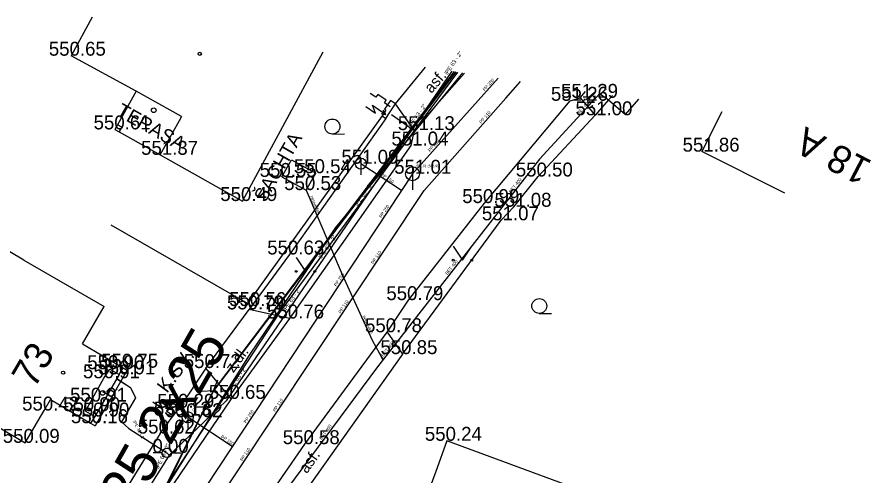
# Model space of a CAD drawing. Extents: x -669995 to -669686, y -1125551 to -1125263.
# Drawn here: x -669817.31 to -669771.34, y -1125299.08 to -1125274.36 of the extents above; entities that cross this region are included whole.
import ezdxf

# ---------------------------------------------------------------- set-up
doc = ezdxf.new("R2010")
doc.units = 0
for name, color, linetype in [('G_Bod_tecka', 7, 'Continuous'), ('G_Bod_vyska', 7, 'Continuous'), ('G_Budovy-znacky', 7, 'Continuous'), ('G_Budovy_Objekty', 7, 'Continuous'), ('G_Budovy_vstupy', 7, 'Continuous'), ('G_Cesty_Schody', 7, 'Continuous'), ('G_Cisla_popisna', 7, 'Continuous'), ('G_Plochy_zpevnene', 7, 'Continuous'), ('G_Ploty', 7, 'Continuous'), ('G_Ploty_vstupy', 7, 'Continuous'), ('G_Popisy_objektu', 7, 'Continuous'), ('G_Popisy_povrchu', 7, 'Continuous'), ('G_Poznamky_odkaz', 7, 'Continuous'), ('G_Site-kanalizace', 7, 'Continuous'), ('G_Site-Rozvadece', 7, 'Continuous'), ('G_Site-vodovod', 7, 'Continuous'), ('G_Z_ELsilove_nadz_kotovane', 7, 'Continuous'), ('G_Z_ELsilove_podz_kotovane', 7, 'Continuous'), ('G_Z_KANAL_podz_kotovane', 7, 'Continuous'), ('G_Z_KANAL_podz_priblizne', 7, 'Continuous'), ('G_Z_PLYNY_podz_geodeticky', 7, 'Continuous'), ('G_Z_SPOJE_podz_geodeticky', 7, 'Continuous'), ('G_Z_SPOJE_podz_kotovane', 7, 'Continuous'), ('G_Z_SPOJE_podz_priblizne', 7, 'Continuous'), ('G_Z_VODA_podz_kotovane', 7, 'Continuous'), ('G_Zelen-okraj', 7, 'Continuous'), ('G_Zelen-Znacky', 7, 'Continuous'), ('Vrstva 11', 7, 'Continuous'), ('Vrstva 13', 7, 'Continuous'), ('Vrstva 17', 7, 'Continuous'), ('Vrstva 2', 7, 'Continuous'), ('Vrstva 21', 7, 'Continuous'), ('Vrstva 26', 7, 'Continuous'), ('Vrstva 3', 7, 'Continuous'), ('Vrstva 4', 7, 'Continuous'), ('Vrstva 5', 7, 'Continuous'), ('Vrstva 6', 7, 'Continuous'), ('Vrstva 8', 7, 'Continuous')]:
    doc.layers.add(name, color=color, linetype=linetype)

msp = doc.modelspace()

# ---------------------------------------------------------------- linework, layer by layer
at = {"layer": 'G_Bod_tecka'}
for p, q in [((-669814.4, -1125276.44), (-669814.4, -1125276.44)), ((-669787, -1125278.71), (-669787, -1125278.71)), ((-669787.53, -1125278.87), (-669787.53, -1125278.87)), ((-669786.18, -1125279.65), (-669786.18, -1125279.65)), ((-669812.05, -1125280.41), (-669812.05, -1125280.41)), ((-669795.93, -1125280.45), (-669795.93, -1125280.45)), ((-669796.11, -1125281.28), (-669796.11, -1125281.28)), ((-669809.61, -1125281.78), (-669809.61, -1125281.78)), ((-669780.44, -1125281.61), (-669780.44, -1125281.61)), ((-669798.8, -1125282.26), (-669798.8, -1125282.26)), ((-669803.06, -1125282.97), (-669803.06, -1125282.97)), ((-669801.22, -1125282.77), (-669801.22, -1125282.77)), ((-669796.02, -1125282.8), (-669796.02, -1125282.8)), ((-669789.25, -1125282.95), (-669789.25, -1125282.95)), ((-669801.74, -1125283.68), (-669801.74, -1125283.68)), ((-669805.18, -1125284.27), (-669805.18, -1125284.27)), ((-669792.15, -1125284.38), (-669792.15, -1125284.38)), ((-669790.56, -1125284.58), (-669790.56, -1125284.58)), ((-669791.24, -1125285.31), (-669791.24, -1125285.31)), ((-669802.64, -1125287.15), (-669802.64, -1125287.15)), ((-669796.24, -1125289.61), (-669796.24, -1125289.61)), ((-669804.82, -1125290.11), (-669804.82, -1125290.11)), ((-669804.69, -1125289.93), (-669804.69, -1125289.93)), ((-669802.65, -1125290.6), (-669802.65, -1125290.6)), ((-669797.39, -1125291.34), (-669797.39, -1125291.34)), ((-669796.56, -1125292.52), (-669796.56, -1125292.52)), ((-669812.32, -1125293.33), (-669812.32, -1125293.33)), ((-669811.6, -1125293.25), (-669811.6, -1125293.25)), ((-669807.15, -1125293.27), (-669807.15, -1125293.27)), ((-669812.63, -1125293.82), (-669812.63, -1125293.82)), ((-669811.81, -1125293.61), (-669811.81, -1125293.61)), ((-669813.33, -1125295.08), (-669813.33, -1125295.08)), ((-669805.79, -1125294.93), (-669805.79, -1125294.93)), ((-669815.85, -1125295.56), (-669815.85, -1125295.56)), ((-669813.62, -1125295.59), (-669813.62, -1125295.59)), ((-669808.9, -1125295.83), (-669808.9, -1125295.83)), ((-669808.57, -1125295.41), (-669808.57, -1125295.41)), ((-669813.35, -1125296.24), (-669813.35, -1125296.24)), ((-669813.12, -1125295.88), (-669813.12, -1125295.88)), ((-669808.12, -1125295.92), (-669808.12, -1125295.92)), ((-669809.61, -1125296.8), (-669809.61, -1125296.8)), ((-669794.17, -1125297.19), (-669794.17, -1125297.19)), ((-669816.87, -1125297.3), (-669816.87, -1125297.3)), ((-669801.82, -1125297.37), (-669801.82, -1125297.37)), ((-669809.24, -1125297.84), (-669809.24, -1125297.84))]:
    msp.add_line(p, q, dxfattribs=at)
at = {"layer": 'G_Budovy-znacky'}
for centre, radius in [((-669807.47, -1125276.34), 0.0875), ((-669809.951, -1125279.38), 0.125), ((-669814.831, -1125293.52), 0.0875), ((-669812.7, -1125294.61), 0.125)]:
    msp.add_circle(centre, radius, dxfattribs=at)
at = {"layer": 'G_Budovy_Objekty'}
for p, q in [((-669813.267, -1125274.359), (-669814.4, -1125276.44)), ((-669810.89, -1125278.35), (-669814.4, -1125276.44)), ((-669805.18, -1125284.27), (-669800.837, -1125276.231)), ((-669810.89, -1125278.35), (-669811.91, -1125280.17)), ((-669808.45, -1125279.72), (-669810.89, -1125278.35)), ((-669808.45, -1125279.72), (-669808.58, -1125279.95)), ((-669779.365, -1125279.465), (-669780.44, -1125281.61)), ((-669811.91, -1125280.17), (-669812.05, -1125280.41)), ((-669811.67, -1125280.3), (-669811.91, -1125280.17)), ((-669812.05, -1125280.41), (-669811.81, -1125280.55)), ((-669811.67, -1125280.3), (-669811.81, -1125280.55)), ((-669811.81, -1125280.55), (-669809.61, -1125281.78)), ((-669809.61, -1125281.78), (-669809.27, -1125281.17)), ((-669809.61, -1125281.78), (-669805.18, -1125284.27)), ((-669775.97, -1125283.85), (-669780.44, -1125281.61)), ((-669816.95, -1125287.46), (-669821.67, -1125284.62)), ((-669816.95, -1125287.46), (-669812.62, -1125289.95)), ((-669813.78, -1125291.97), (-669812.62, -1125289.95)), ((-669813.78, -1125291.97), (-669811.6, -1125293.25)), ((-669812.63, -1125293.82), (-669812.32, -1125293.33)), ((-669812.32, -1125293.33), (-669811.81, -1125293.61)), ((-669811.81, -1125293.61), (-669811.6, -1125293.25)), ((-669811.81, -1125293.61), (-669813.12, -1125295.88)), ((-669821.18, -1125294.77), (-669816.87, -1125297.3)), ((-669815.85, -1125295.56), (-669815.51, -1125294.97)), ((-669815.51, -1125294.97), (-669813.35, -1125296.24)), ((-669813.62, -1125295.59), (-669813.33, -1125295.08)), ((-669816.87, -1125297.3), (-669815.85, -1125295.56)), ((-669813.62, -1125295.59), (-669813.12, -1125295.88)), ((-669813.12, -1125295.88), (-669813.35, -1125296.24)), ((-669794.17, -1125297.19), (-669794.77, -1125298.84)), ((-669779.82, -1125302.48), (-669794.17, -1125297.19))]:
    msp.add_line(p, q, dxfattribs=at)
at = {"layer": 'G_Budovy_vstupy'}
for p, q in [((-669808.58, -1125279.95), (-669809.27, -1125281.17)), ((-669813.33, -1125295.08), (-669812.63, -1125293.82)), ((-669794.77, -1125298.84), (-669796.57, -1125303.72))]:
    msp.add_line(p, q, dxfattribs=at)
at = {"layer": 'G_Cesty_Schody'}
for p, q in [((-669803.06, -1125282.97), (-669802.54, -1125282.06)), ((-669802.54, -1125282.06), (-669801.22, -1125282.77)), ((-669803.06, -1125282.97), (-669801.74, -1125283.68)), ((-669801.74, -1125283.68), (-669801.22, -1125282.77))]:
    msp.add_line(p, q, dxfattribs=at)
for points in [[(-669793.221, -1125277.378), (-669795.93, -1125280.45)], [(-669802.65, -1125290.6), (-669805.79, -1125294.93)]]:
    msp.add_lwpolyline(points, dxfattribs=at)
at = {"layer": 'G_Plochy_zpevnene'}
for p, q in [((-669787, -1125278.71), (-669786.18, -1125279.65)), ((-669785.96, -1125278.472), (-669785.46, -1125278.82)), ((-669795.93, -1125280.45), (-669796.93, -1125279.04)), ((-669792.15, -1125284.38), (-669787.53, -1125278.87)), ((-669796.24, -1125289.61), (-669792.15, -1125284.38)), ((-669797.39, -1125291.34), (-669796.24, -1125289.61)), ((-669801.82, -1125297.37), (-669797.39, -1125291.34)), ((-669811.38, -1125293.38), (-669813.11, -1125296.38)), ((-669811.6, -1125293.25), (-669811.38, -1125293.38)), ((-669813.35, -1125296.24), (-669813.11, -1125296.38)), ((-669804.96, -1125301.91), (-669801.82, -1125297.37))]:
    msp.add_line(p, q, dxfattribs=at)
for points in [[(-669787, -1125278.71), (-669786.697, -1125278.361)], [(-669787.53, -1125278.87), (-669787, -1125278.71)], [(-669795.93, -1125280.45), (-669796.11, -1125281.28), (-669802.65, -1125290.6)], [(-669802.65, -1125290.6), (-669804.82, -1125290.11)], [(-669797.39, -1125291.34), (-669796.56, -1125292.52)], [(-669805.79, -1125294.93), (-669807.15, -1125293.27)], [(-669805.79, -1125294.93), (-669810.6, -1125302.02), (-669813.3, -1125306.54), (-669816.06, -1125312.52), (-669819.42, -1125319.54), (-669819.78, -1125320.24), (-669820.3, -1125320.5), (-669820.46, -1125320.59)]]:
    msp.add_lwpolyline(points, dxfattribs=at)
at = {"layer": 'G_Ploty'}
for p, q in [((-669785.46, -1125278.82), (-669785.251, -1125278.579)), ((-669797.66, -1125279.68), (-669804.91, -1125289.8)), ((-669789.25, -1125282.95), (-669786.18, -1125279.65)), ((-669804.91, -1125289.8), (-669812.24, -1125285.58)), ((-669804.69, -1125289.93), (-669804.91, -1125289.8)), ((-669804.69, -1125289.93), (-669804.82, -1125290.11))]:
    msp.add_line(p, q, dxfattribs=at)
for points in [[(-669797.45, -1125279.82), (-669802.64, -1125287.15), (-669804.69, -1125289.93)], [(-669790.56, -1125284.58), (-669789.25, -1125282.95)], [(-669796.56, -1125292.52), (-669791.24, -1125285.31)], [(-669807.15, -1125293.27), (-669808.57, -1125295.41)], [(-669809.61, -1125296.8), (-669814.94, -1125305.46)]]:
    msp.add_lwpolyline(points, dxfattribs=at)
at = {"layer": 'G_Ploty_vstupy'}
for p, q in [((-669796.93, -1125279.04), (-669795.318, -1125277.062)), ((-669785.46, -1125278.82), (-669786.18, -1125279.65)), ((-669790.56, -1125284.58), (-669791.24, -1125285.31))]:
    msp.add_line(p, q, dxfattribs=at)
for points in [[(-669807.15, -1125293.27), (-669804.82, -1125290.11)], [(-669796.56, -1125292.52), (-669802.85, -1125301.41)], [(-669809.61, -1125296.8), (-669808.9, -1125295.85)]]:
    msp.add_lwpolyline(points, dxfattribs=at)
at = {"layer": 'G_Site-kanalizace'}
for p, q in [((-669798.8, -1125281.96), (-669798.8, -1125282.86)), ((-669796.02, -1125282.425), (-669796.02, -1125283.675)), ((-669808.12, -1125295.62), (-669808.12, -1125296.52))]:
    msp.add_line(p, q, dxfattribs=at)
for centre, radius in [((-669798.8, -1125282.26), 0.3), ((-669796.02, -1125282.8), 0.375), ((-669808.12, -1125295.92), 0.3)]:
    msp.add_circle(centre, radius, dxfattribs=at)
at = {"layer": 'G_Site-Rozvadece'}
for p, q in [((-669798.526, -1125279.183), (-669798.005, -1125279.53)), ((-669798.005, -1125279.53), (-669798.178, -1125279.114)), ((-669798.178, -1125279.114), (-669797.45, -1125279.6)), ((-669797.715, -1125279.555), (-669797.45, -1125279.6)), ((-669797.45, -1125279.6), (-669797.593, -1125279.372)), ((-669810.001, -1125295.093), (-669809.484, -1125295.445)), ((-669809.484, -1125295.445), (-669809.653, -1125295.028)), ((-669809.653, -1125295.028), (-669808.93, -1125295.52)), ((-669808.93, -1125295.52), (-669809.07, -1125295.291)), ((-669809.194, -1125295.473), (-669808.93, -1125295.52))]:
    msp.add_line(p, q, dxfattribs=at)
msp.add_lwpolyline([(-669797.23, -1125279.19), (-669797.535, -1125278.985), (-669797.434, -1125278.833), (-669797.893, -1125278.526), (-669797.996, -1125278.678), (-669798.302, -1125278.475)], dxfattribs=at)
for points in [[(-669796.93, -1125279.04), (-669797.21, -1125278.85), (-669797.53, -1125279.33), (-669797.46, -1125279.38), (-669797.66, -1125279.68), (-669797.45, -1125279.82), (-669797.25, -1125279.52)], [(-669808.93, -1125295.14), (-669809.26, -1125295.58), (-669808.9, -1125295.85), (-669808.57, -1125295.41)]]:
    msp.add_lwpolyline(points, close=True, dxfattribs=at)
at = {"layer": 'G_Site-vodovod'}
for p, q in [((-669809.49, -1125297.84), (-669809.99, -1125297.84)), ((-669808.99, -1125297.84), (-669808.49, -1125297.84))]:
    msp.add_line(p, q, dxfattribs=at)
msp.add_circle((-669809.24, -1125297.84), 0.25, dxfattribs=at)
at = {"layer": 'G_Z_ELsilove_nadz_kotovane'}
for points in [[(-669822.83, -1125326.67), (-669806.73, -1125294.49), (-669793.764, -1125277.296)], [(-669806.73, -1125294.49), (-669806.505, -1125293.909)], [(-669806.73, -1125294.49), (-669807.359, -1125294.525)], [(-669806.73, -1125294.49), (-669806.213, -1125294.859)]]:
    msp.add_lwpolyline(points, dxfattribs=at)
at = {"layer": 'G_Z_ELsilove_podz_kotovane'}
msp.add_lwpolyline([(-669793.678, -1125277.309), (-669806.73, -1125294.49), (-669822.69, -1125326.67), (-669837.43, -1125364.93), (-669849.93, -1125407.07), (-669860.28, -1125448.68)], dxfattribs=at)
at = {"layer": 'G_Z_KANAL_podz_kotovane'}
for p, q in [((-669791.4, -1125277.652), (-669796.02, -1125282.8)), ((-669796.62, -1125283.7), (-669798.8, -1125282.26))]:
    msp.add_line(p, q, dxfattribs=at)
for points in [[(-669837.47, -1125406.42), (-669844.1, -1125405.26), (-669833.36, -1125371.21), (-669821.31, -1125332.23), (-669811.44, -1125307.86), (-669795.39, -1125283.71), (-669791, -1125278.72), (-669790.199, -1125277.833)], [(-669796.62, -1125283.7), (-669798.8, -1125282.26)], [(-669796.02, -1125282.8), (-669812.36, -1125307.58), (-669819.67, -1125324.06)], [(-669801.74, -1125283.68), (-669799.8, -1125288.23), (-669798.19, -1125291.77), (-669797.79, -1125292.49), (-669797.61, -1125292.82)], [(-669805.72, -1125297.5), (-669805.72, -1125297.5), (-669808.12, -1125295.92)]]:
    msp.add_lwpolyline(points, dxfattribs=at)
at = {"layer": 'G_Z_KANAL_podz_priblizne'}
msp.add_lwpolyline([(-669785.926, -1125278.477), (-669789.18, -1125282.01), (-669797.9, -1125293.2), (-669805.95, -1125304.06)], dxfattribs=at)
at = {"layer": 'G_Z_PLYNY_podz_geodeticky'}
for points in [[(-669837.38, -1125359.92), (-669836.39, -1125358.74), (-669831.49, -1125357.25), (-669831.11, -1125356.92), (-669827.75, -1125345.68), (-669825.44, -1125337.89), (-669825.15, -1125336.78), (-669824.89, -1125336.1), (-669824.26, -1125333.86), (-669824.2, -1125333.72), (-669824.11, -1125333.34), (-669824.01, -1125332.89), (-669822.73, -1125329.33), (-669822.53, -1125328.7), (-669820.54, -1125322.64), (-669816.69, -1125313.26), (-669812.22, -1125303.65), (-669812, -1125303.3), (-669811.72, -1125302.91), (-669809.57, -1125300.17), (-669804.79, -1125292.58), (-669800.14, -1125285.7), (-669795.88, -1125280.51), (-669793.302, -1125277.366)], [(-669797.15, -1125279.61), (-669795.88, -1125280.51)]]:
    msp.add_lwpolyline(points, dxfattribs=at)
at = {"layer": 'G_Z_SPOJE_podz_geodeticky'}
msp.add_lwpolyline([(-669821.65, -1125324.81), (-669819.63, -1125318.51), (-669812.69, -1125304.83), (-669803.17, -1125290.27), (-669793.576, -1125277.325)], dxfattribs=at)
at = {"layer": 'G_Z_SPOJE_podz_kotovane'}
msp.add_lwpolyline([(-669821.65, -1125324.81), (-669819.63, -1125318.51), (-669812.69, -1125304.83), (-669803.17, -1125290.27), (-669793.576, -1125277.325)], dxfattribs=at)
at = {"layer": 'G_Z_SPOJE_podz_priblizne'}
msp.add_lwpolyline([(-669821.65, -1125324.81), (-669819.63, -1125318.51), (-669812.69, -1125304.83), (-669803.17, -1125290.27), (-669793.576, -1125277.325)], dxfattribs=at)
at = {"layer": 'G_Z_VODA_podz_kotovane'}
for points in [[(-669793.904, -1125277.275), (-669806.05, -1125295.04), (-669809.12, -1125297.97), (-669810.25, -1125299.77), (-669811.13, -1125301.2), (-669814.74, -1125307.05), (-669820.1, -1125318), (-669821.98, -1125322.82), (-669822.36, -1125327.56), (-669822.7, -1125328.38), (-669827.24, -1125342.56), (-669833.54, -1125362.52), (-669834.09, -1125363.24)], [(-669811.94, -1125293.84), (-669811.2, -1125294.32), (-669810.93, -1125294.88), (-669811.69, -1125296.16), (-669811.3, -1125296.52), (-669809.24, -1125297.84), (-669809.12, -1125297.97)]]:
    msp.add_lwpolyline(points, dxfattribs=at)
at = {"layer": 'G_Zelen-okraj'}
for p, q in [((-669785.46, -1125278.82), (-669784.55, -1125279.61)), ((-669784.55, -1125279.61), (-669783.841, -1125278.791))]:
    msp.add_line(p, q, dxfattribs=at)
at = {"layer": 'G_Zelen-Znacky'}
for p, q in [((-669800.332, -1125280.66), (-669799.682, -1125280.657)), ((-669793.83, -1125286.71), (-669793.33, -1125287.46)), ((-669793.33, -1125287.46), (-669792.83, -1125286.71)), ((-669802.28, -1125287.31), (-669801.78, -1125288.06)), ((-669801.78, -1125288.06), (-669801.28, -1125287.31)), ((-669789.192, -1125290.33), (-669788.542, -1125290.327))]:
    msp.add_line(p, q, dxfattribs=at)
for centre, radius in [((-669800.332, -1125280.257), 0.403), ((-669793.83, -1125287.46), 0.05), ((-669792.83, -1125287.46), 0.05), ((-669802.28, -1125288.06), 0.05), ((-669801.28, -1125288.06), 0.05), ((-669789.192, -1125289.927), 0.403)]:
    msp.add_circle(centre, radius, dxfattribs=at)
at = {"layer": 'Vrstva 11'}
for p, q in [((-669791.4, -1125277.652), (-669796.02, -1125282.8)), ((-669796.62, -1125283.7), (-669798.8, -1125282.26))]:
    msp.add_line(p, q, dxfattribs=at)
for points in [[(-669796.62, -1125283.7), (-669798.8, -1125282.26)], [(-669796.02, -1125282.8), (-669812.36, -1125307.58), (-669819.67, -1125324.06)], [(-669805.715, -1125297.503), (-669805.72, -1125297.5), (-669808.12, -1125295.92)]]:
    msp.add_lwpolyline(points, dxfattribs=at)
at = {"layer": 'Vrstva 13'}
msp.add_lwpolyline([(-669801.74, -1125283.68), (-669799.8, -1125288.23), (-669798.19, -1125291.77), (-669797.79, -1125292.49), (-669797.605, -1125292.822)], dxfattribs=at)
at = {"layer": 'Vrstva 17'}
msp.add_lwpolyline([(-669785.926, -1125278.477), (-669789.18, -1125282.01), (-669797.9, -1125293.2), (-669805.95, -1125304.06)], dxfattribs=at)
at = {"layer": 'Vrstva 21'}
msp.add_lwpolyline([(-669837.47, -1125406.42), (-669844.1, -1125405.26), (-669833.36, -1125371.21), (-669821.31, -1125332.23), (-669811.44, -1125307.86), (-669795.39, -1125283.71), (-669791, -1125278.72), (-669790.199, -1125277.833)], dxfattribs=at)
at = {"layer": 'Vrstva 26'}
for points in [[(-669793.906, -1125277.275), (-669806.05, -1125295.04), (-669809.12, -1125297.97), (-669810.25, -1125299.77), (-669811.134, -1125301.203), (-669814.74, -1125307.05), (-669820.1, -1125318), (-669821.98, -1125322.82), (-669822.36, -1125327.56), (-669822.7, -1125328.38), (-669827.24, -1125342.56), (-669833.535, -1125362.519), (-669834.09, -1125363.24)], [(-669811.944, -1125293.843), (-669811.2, -1125294.32), (-669810.93, -1125294.88), (-669811.69, -1125296.16), (-669811.3, -1125296.52), (-669809.24, -1125297.84), (-669809.12, -1125297.97)]]:
    msp.add_lwpolyline(points, dxfattribs=at)
at = {"layer": 'Vrstva 5'}
for p, q in [((-669793.678, -1125277.309), (-669806.73, -1125294.49)), ((-669806.73, -1125294.49), (-669822.69, -1125326.67))]:
    msp.add_line(p, q, dxfattribs=at)
at = {"layer": 'Vrstva 6'}
msp.add_line((-669809.24, -1125297.84), (-669809.24, -1125297.84), dxfattribs=at)
at = {"layer": 'Vrstva 8'}
for p, q in [((-669798.8, -1125282.26), (-669798.8, -1125282.26)), ((-669796.02, -1125282.8), (-669796.02, -1125282.8)), ((-669808.12, -1125295.92), (-669808.12, -1125295.92))]:
    msp.add_line(p, q, dxfattribs=at)

# ---------------------------------------------------------------- texts
at = {"layer": 'G_Bod_vyska'}
for s, p in [('550.65', (-669815.599, -1125276.44)), ('551.26', (-669788.566, -1125278.87)), ('551.29', (-669788.024, -1125278.71)), ('551.00', (-669787.246, -1125279.65)), ('550.61', (-669813.188, -1125280.41)), ('551.13', (-669796.811, -1125280.45)), ('551.04', (-669797.154, -1125281.28)), ('551.37', (-669810.632, -1125281.78)), ('551.86', (-669781.476, -1125281.61)), ('551.09', (-669799.846, -1125282.26)), ('550.54', (-669802.406, -1125282.77)), ('551.01', (-669797.002, -1125282.8)), ('550.55', (-669804.246, -1125282.97)), ('550.50', (-669790.457, -1125282.95)), ('550.53', (-669802.926, -1125283.68)), ('550.49', (-669806.368, -1125284.27)), ('550.99', (-669793.34, -1125284.38)), ('551.08', (-669791.604, -1125284.58)), ('551.07', (-669792.284, -1125285.31)), ('550.63', (-669803.839, -1125287.15)), ('550.79', (-669797.428, -1125289.61)), ('550.79', (-669806.008, -1125290.11)), ('550.56', (-669805.889, -1125289.93)), ('550.76', (-669803.849, -1125290.6)), ('550.78', (-669798.576, -1125291.34)), ('550.85', (-669797.746, -1125292.52)), ('550.90', (-669813.529, -1125293.33)), ('550.75', (-669812.786, -1125293.25)), ('550.72', (-669808.336, -1125293.27)), ('550.91', (-669813.756, -1125293.82)), ('550.91', (-669812.936, -1125293.61)), ('550.91', (-669814.456, -1125295.08)), ('550.65', (-669806.989, -1125294.93)), ('550.42', (-669817.036, -1125295.56)), ('550.90', (-669814.829, -1125295.59)), ('550.29', (-669809.758, -1125295.41)), ('550.90', (-669814.329, -1125295.88)), ('550.13', (-669809.944, -1125295.83)), ('550.62', (-669809.319, -1125295.92)), ('550.16', (-669814.408, -1125296.24)), ('550.62', (-669810.809, -1125296.8)), ('550.09', (-669818.079, -1125297.3)), ('550.58', (-669803.006, -1125297.37)), ('550.24', (-669795.353, -1125297.19)), ('0.00', (-669810.02, -1125297.84))]:
    msp.add_text(s, height=0.75, dxfattribs=at).set_placement(p)
at = {"layer": 'G_Cisla_popisna'}
for s, rotation, p in [('18 A', 152.4129, (-669771.203, -1125282.15)), ('73', 59.6209, (-669816.381, -1125294.412))]:
    msp.add_text(s, height=1.5, rotation=rotation, dxfattribs=at).set_placement(p)
at = {"layer": 'G_Popisy_objektu'}
msp.add_text('K.SV.', height=0.75, rotation=53.664, dxfattribs=at).set_placement((-669809.235, -1125294.659))
at = {"layer": 'G_Popisy_povrchu'}
for s, rotation, p in [('asf.', 48.5953, (-669795.003, -1125278.504)), ('b.', 311.0392, (-669786.75, -1125278.757)), ('z.dl.', 54.0514, (-669805.669, -1125293.566)), ('b.', 60.0233, (-669812.201, -1125294.933)), ('asf.', 54.7192, (-669801.706, -1125298.993))]:
    msp.add_text(s, height=0.6, rotation=rotation, dxfattribs=at).set_placement(p)
at = {"layer": 'G_Poznamky_odkaz'}
for s, rotation, p in [('TERASA', 330.67, (-669812.022, -1125279.623)), ('ŠACHTA', 60.2551, (-669803.949, -1125284.391))]:
    msp.add_text(s, height=0.75, rotation=rotation, dxfattribs=at).set_placement(p)
at = {"layer": 'Vrstva 2'}
for s, height, p in [('\xa0()', 0.1316, (-669798.595, -1125281.907)), ('551.01 (548.99)', 0.13163, (-669795.814, -1125282.447)), ('\xa0()', 0.1316, (-669807.915, -1125295.567))]:
    msp.add_text(s, height=height, dxfattribs=at).set_placement(p)
at = {"layer": 'Vrstva 3'}
for s, height, rotation, p in [('PP 250', 0.1755, 48.1168, (-669792.128, -1125278.358)), ('BET 400', 0.1755, 47.4141, (-669787.07, -1125279.617)), ('PP 110', 0.1755, 48.6436, (-669792.318, -1125280.112)), ('PP 250', 0.1755, 48.1718, (-669795.077, -1125281.644)), ('PP 150', 0.1755, 326.527, (-669797.754, -1125282.888)), ('BET 400', 0.1755, 52.0231, (-669790.708, -1125283.859)), ('neuveden', 0.1755, 293.1395, (-669801.534, -1125284.025)), ('PP 250', 0.1755, 56.5614, (-669797.689, -1125285.204)), ('PP 110', 0.1755, 56.4013, (-669798.12, -1125287.69)), ('BET 400', 0.1755, 52.0921, (-669794.143, -1125288.264)), ('PP 250', 0.1755, 56.6068, (-669800.119, -1125288.89)), ('PP 110', 0.1755, 56.4699, (-669799.883, -1125290.343)), ('neuveden', 0.1755, 294.4827, (-669798.72, -1125290.48)), ('NFA2X 2x25 2x25', 2.19389, 60.2692, (-669817.715, -1125312.66)), ('BET 400', 0.1755, 52.0382, (-669797.577, -1125292.671)), ('PP 110', 0.1755, 56.39, (-669803.409, -1125295.648)), ('PP 250', 0.1755, 56.6412, (-669804.98, -1125296.262)), ('BET 400', 0.1755, 53.4854, (-669800.916, -1125297.152)), ('PP 150', 0.1755, 326.6068, (-669806.36, -1125297.015)), ('PP 110', 0.1755, 56.4128, (-669805.172, -1125298.301))]:
    msp.add_text(s, height=height, rotation=rotation, dxfattribs=at).set_placement(p)
at = {"layer": 'Vrstva 4'}
for s, height, rotation, p in [('lPE 63 - 2"', 0.21938, 55.6477, (-669794.138, -1125277.488)), ('lPE 63 - 2"', 0.21938, 55.6477, (-669796.072, -1125280.318)), ('lPE 63 - 2"', 0.21938, 55.5701, (-669798.973, -1125284.563)), ('lPE 63 - 2"', 0.21938, 55.6477, (-669800.908, -1125287.392)), ('lPE 63 - 2"', 0.21938, 55.5701, (-669802.842, -1125290.222)), ('lPE 63 - 2"', 0.21938, 55.045, (-669805.751, -1125294.459)), ('lPE 32 - 1"', 0.17551, 296.7214, (-669811.08, -1125296.144)), ('lPE 63 - 2"', 0.21938, 65.4099, (-669809.668, -1125298.716))]:
    msp.add_text(s, height=height, rotation=rotation, dxfattribs=at).set_placement(p)

doc.saveas('drawing.dxf')
